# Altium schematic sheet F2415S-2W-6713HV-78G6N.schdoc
size 277 x 190 mm; Device: default297x210; Symbol: default297x210; Name: default297x210; Date: 2025.06.26; Rev: V1.1; Size: "A4"; Id: /; File: F2415S-2W-6713HV-78G6N; Sheet: /; @Page No: 1; @Page Count: 1; @Schematic Name: F2415S-2W-6713HV-78G6N; @Project Name: 全桥隔离电源-F2415S-2W-6713HV-78G6N; @Board Name: F2415S-2W-6713HV-78G6N; @Update Date: 2025-07-16; @Create Time: 09:58:00; @Update Time: 11:23:18; @Page Name: F2415S-2W-6713HV-78G6N; @Create Date: 2025-06-26
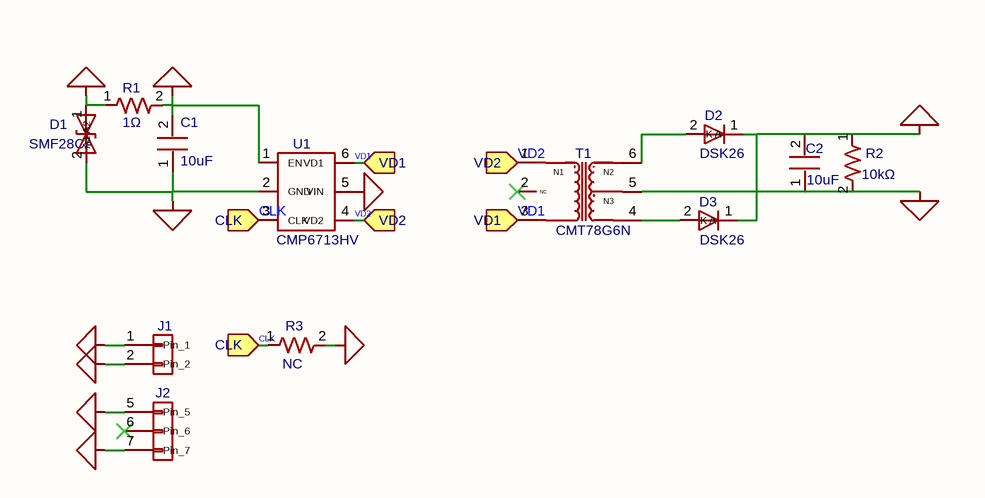
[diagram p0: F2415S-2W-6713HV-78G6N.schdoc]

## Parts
C1  10uF  [C0603]
C2  10uF  [C0603]
D1  SMF28CA  [SOD-123FL_L2.8-W1.8-LS3.7-BI]
D2  DSK26  [SOD-123_L2.8-W1.8-LS3.7-RD]
D3  DSK26  [SOD-123_L2.8-W1.8-LS3.7-RD]
J1  (no value)  [coileasy:PinHeader_01x02_P2.54mm_Vertical]
J2  Connector_Generic_Conn_01x03  [coileasy:PinHeader_01x03_1_P2.54mm_Vertical]  (value not drawn)
R1  1Ω  [R0603]
R2  10kΩ  [R0603]
R3  NC  [R0603]
T1  CMT78G6N  [XFMR-SMD_6P-L9.3-W8.8-P2.54-LS12.6]
U1  CMP6713HV  [coileasy:SOT-23-6]

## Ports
CLK (in), VD1 (in), VD2 (in)

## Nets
0V: C2.1 J2.5(Pin_5) R2.2 T1.5
+VO: C2.2 D2.1(K) D3.1(K) J2.7(Pin_7) R2.1
GND: C1.1 D1.2(A2) J1.2(Pin_2) R3.2 U1.2(GND)
VCC: C1.2 R1.2 U1.1(EN) U1.5(VIN)
VIN: D1.1(A1) J1.1(Pin_1) R1.1
CLK: R3.1 U1.3(CLK) ; port CLK
VD1: T1.3 U1.6(VD1) ; port VD1
VD2: T1.1 U1.4(VD2) ; port VD2
NetD2_2: D2.2(A) T1.6
NetD3_2: D3.2(A) T1.4

Not connected (* = marked no-connect by the designer): J2 6(Pin_6)*; T1 2*

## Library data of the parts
C1 = CGA0603X5R106M350JT: 容值:10uF;精度:±20%;额定电压:35V;温度系数:X5R;; Manufacturer: HRE(芯声); Symbol: My_Library_C; AddInBom: yes; ModelId: ac125912035d415993ca9572d50418b1; ModelName: C0603_L1.6-W0.8-H0.8; ModelTransform: 62.992,31.496,0,0,0,0,0,0,0; Tolerance: ±20%; Voltage Rating: 35V; Temperature Coefficient: X5R
C2 = 0603X106M250NT: 容值:10uF;精度:±20%;额定电压:25V;温度系数:X5R;; Manufacturer: FH(风华); Symbol: My_Library_C; AddInBom: yes; ModelId: ac125912035d415993ca9572d50418b1; ModelName: C0603_L1.6-W0.8-H0.8; ModelTransform: 62.992,31.496,0,0,0,0,0,0,0; Tolerance: ±20%; Voltage Rating: 25V; Temperature Coefficient: X5R
D1 = SMF28CA_C364280: 极性:双向;反向截止电压(Vrwm):28V;最大钳位电压:45.4V;峰值脉冲电流(Ipp):4.4A;峰值脉冲功率(Ppp):200W;击穿电压:34.4V;; Manufacturer: MDD(辰达半导体); Symbol: Device_D_TVS; AddInBom: yes; ModelId: d105299b3871451c86f679efef28ff8f; ModelTransform: 145.669,70.866,0,0,0,0,0,0,0; polarity: 双向; Reverse Stand-Off Voltage (Vrwm): 28V; Maximum Clamping Voltage: 45.4V; Peak Pulse Current (Ipp): 4.4A; Peak Pulse Power Dissipation (Ppp): 200W; Breakdown Voltage: 34.4V; Reverse Leakage Current (Ir): 1uA; Type: TVS
D2 D3 = DSK26_C50553: 二极管配置:独立式;正向压降(Vf):700mV@2A;直流反向耐压(Vr):60V;整流电流:2A;; Manufacturer: MDD(辰达半导体); Symbol: My_Library_D; AddInBom: yes; ModelId: 7884390a25fb4c08947731ebfba7e3f8; ModelTransform: 144.8816,62.992,0,0,0,0,0,0,0; Diode Configuration: 独立式; Reverse Voltage (Vr): 60V; Rectified Current: 2A; Reverse Leakage Current (Ir): 500uA@60V
J1 = Connector_Generic_Conn_01x02: Symbol: Conn_01x04_1; AddInBom: yes
J2 = Connector_Generic_Conn_01x03: Symbol: Connector_Generic_Conn_01x04; AddInBom: yes
R1 = RC0603FR-071RL: 电阻类型:厚膜电阻;阻值:1Ω;精度:±1%;功率:100mW;最大工作电压:75V;温度系数:±200ppm/℃;; Manufacturer: YAGEO(国巨); Symbol: My_Library_R; AddInBom: yes; ModelId: fc143cca1e79419f9cd78b61e9279f08; ModelTransform: 31.8897,63.7794,0,90,0,0,0,0,0; Tolerance: ±1%; Power(Watts): 100mW; Overload Voltage (Max): 75V
R2 = RC0603FR-0710KL: 电阻类型:厚膜电阻;阻值:10kΩ;精度:±1%;功率:100mW;最大工作电压:75V;温度系数:±100ppm/℃;; Manufacturer: YAGEO(国巨); Symbol: My_Library_R; AddInBom: yes; ModelId: fc143cca1e79419f9cd78b61e9279f08; ModelTransform: 31.8897,63.7794,0,90,0,0,0,0,0; Tolerance: ±1%; Power(Watts): 100mW; Overload Voltage (Max): 75V
R3 = RC0603FR-0715KL: 电阻类型:厚膜电阻;阻值:15kΩ;精度:±1%;功率:100mW;最大工作电压:75V;温度系数:±100ppm/℃;; Symbol: My_Library_R; AddInBom: yes; ModelId: fc143cca1e79419f9cd78b61e9279f08; ModelTransform: 31.8897,63.7794,0,90,0,0,0,0,0; Tolerance: ±1%; Power(Watts): 100mW; Overload Voltage (Max): 75V
T1 = CMT78G6N: Manufacturer: coileasy(线易); Symbol: MYLibrary _CMT6870N; AddInBom: yes
U1 = CMP6713HV: CMP6713HV 是全桥式变压器驱动器，芯片内部集成两个 N 型功率 MOSFET 和两个 P 型功率 MOSFET，通过内部振荡器提供具有精准时序和死区时间的互补驱动信号。驱动器搭配配套的变压器，可以实现输入电压6.5V-30V, 输出功率不超过 2W 的隔离电源。采用不同的变压器，外围只需搭配简单的输入输出滤波电容，隔离变压器和整流电路，即可获得多种电压的非稳压输出。产品提供电阻选频功能，可以在 200-420 kHz 范围内连续调整开关频率。; Manufacturer: coileasy(线易); Symbol: Coileasy_SOT23-6; AddInBom: yes; ModelId: 18da8f6c14a34920b3e136b5c401a119; ModelName: SOT-23-6_L2.9-W1.6-H1.5-LS2.8-P0.95; ModelTransform: 110.73671,114.173,0,180,0,0,0.001,-0.003,0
